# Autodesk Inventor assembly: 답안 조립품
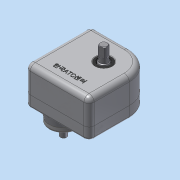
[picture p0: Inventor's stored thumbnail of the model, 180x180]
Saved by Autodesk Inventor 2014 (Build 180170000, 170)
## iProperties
Created: 2015-11
Part Number: 답안 조립품
Document SubType Name: Assembly
Designer: dgall
Author: dgall
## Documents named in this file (13)
- C:\Users\dgall\Desktop\2급\Inventor2급-윤지은\답안 조립품.iam
- C:\Users\dgall\Desktop\2급\Inventor2급-윤지은\본체.ipt
- C:\Users\dgall\Desktop\2급\Inventor2급-윤지은\앞커버.ipt
- C:\Users\dgall\Desktop\2급\Inventor2급-윤지은\베어링 6002.ipt
- C:\Users\dgall\Desktop\2급\Inventor2급-윤지은\축 커버.ipt
- C:\Users\dgall\Desktop\2급\Inventor2급-윤지은\베어링 6001.ipt
- C:\Users\dgall\Desktop\2급\Inventor2급-윤지은\로드 축.ipt
- C:\Users\dgall\Desktop\2급\Inventor2급-윤지은\편심 축.ipt
- C:\Users\dgall\Desktop\2급\Inventor2급-윤지은\로드.ipt
- C:\Users\dgall\Desktop\2급\Inventor2급-윤지은\오일실 15 x 25.ipt
- C:\Users\dgall\Desktop\2급\Inventor2급-윤지은\오일실 12 x 22.ipt
- C:\Users\dgall\Desktop\2급\Inventor2급-윤지은\M4 x 0.7.ipt
- C:\Users\dgall\Desktop\2급\Inventor2급-윤지은\M3 x 0.5.ipt
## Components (9 placed, 2 different names)
1. M4 x 0.7:1
2. M4 x 0.7:2
3. M4 x 0.7:3
4. M4 x 0.7:4
5. M4 x 0.7:5
6. M3 x 0.5:1
7. M3 x 0.5:2
8. M3 x 0.5:3
9. M3 x 0.5:4
